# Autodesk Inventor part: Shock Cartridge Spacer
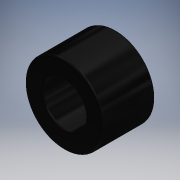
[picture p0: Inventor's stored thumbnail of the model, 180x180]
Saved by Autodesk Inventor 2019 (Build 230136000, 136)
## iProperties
Shininess: 50.0
Compacted: True
Length Units: 11272
Angle Units: 11279
Time Units: 11290
Mass Units: 11286
Length Display Precision: 4
Angle Display Precision: 2
Company: Autodesk
Created: 2000-03
Part Number: Shock Cartridge Spacer
Project: Inventor Samples
User Status: IN PROGRESS
Document SubType Name: Modeling
Designer: Autodesk, Inc.
Density: 1.13 g/cm^3
Mass: 0.106006 g
Surface Area: 1.70274 cm^2
Volume: 0.0938102 cm^3
Material: Nylon-6/6
Appearance: Glossy - Black
Density: 0.0
Volumn: 0.0
Area: 0.0
PropertySet Name: Model Information
Control State: 0
Master: False
Checked Out: False
Checked Out Date: 2018-05-30
Last Check In Date: 2018-05-30
Author: Autodesk, Inc.
Revision Number: A
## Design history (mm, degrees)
node "Extrusion1" dims "d2" = 4.191, "d3" = 0
  sketch "Sketch2"
    geometry: C1 r 3.175 at (2.636, -4.055); C2 r 1.715 at (2.636, -4.055)
    constraints: 2 centre point, 1 coincident
    dimensions: "d0" = 6.35 diameter of C1; "d1" = 3.429 diameter of C2
node "Fillet1" dims "d4" = 0.127
body "Solid1"
